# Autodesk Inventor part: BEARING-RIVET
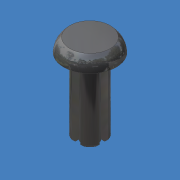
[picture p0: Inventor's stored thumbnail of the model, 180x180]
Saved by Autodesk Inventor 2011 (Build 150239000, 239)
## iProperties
Created: 2007-10
Part Number: BEARING-RIVET
Document SubType Name: Modeling
Material: Delrin, Black
Density: 1.425 g/cm^3
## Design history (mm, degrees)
feature "Base1"
body "Solid1"
